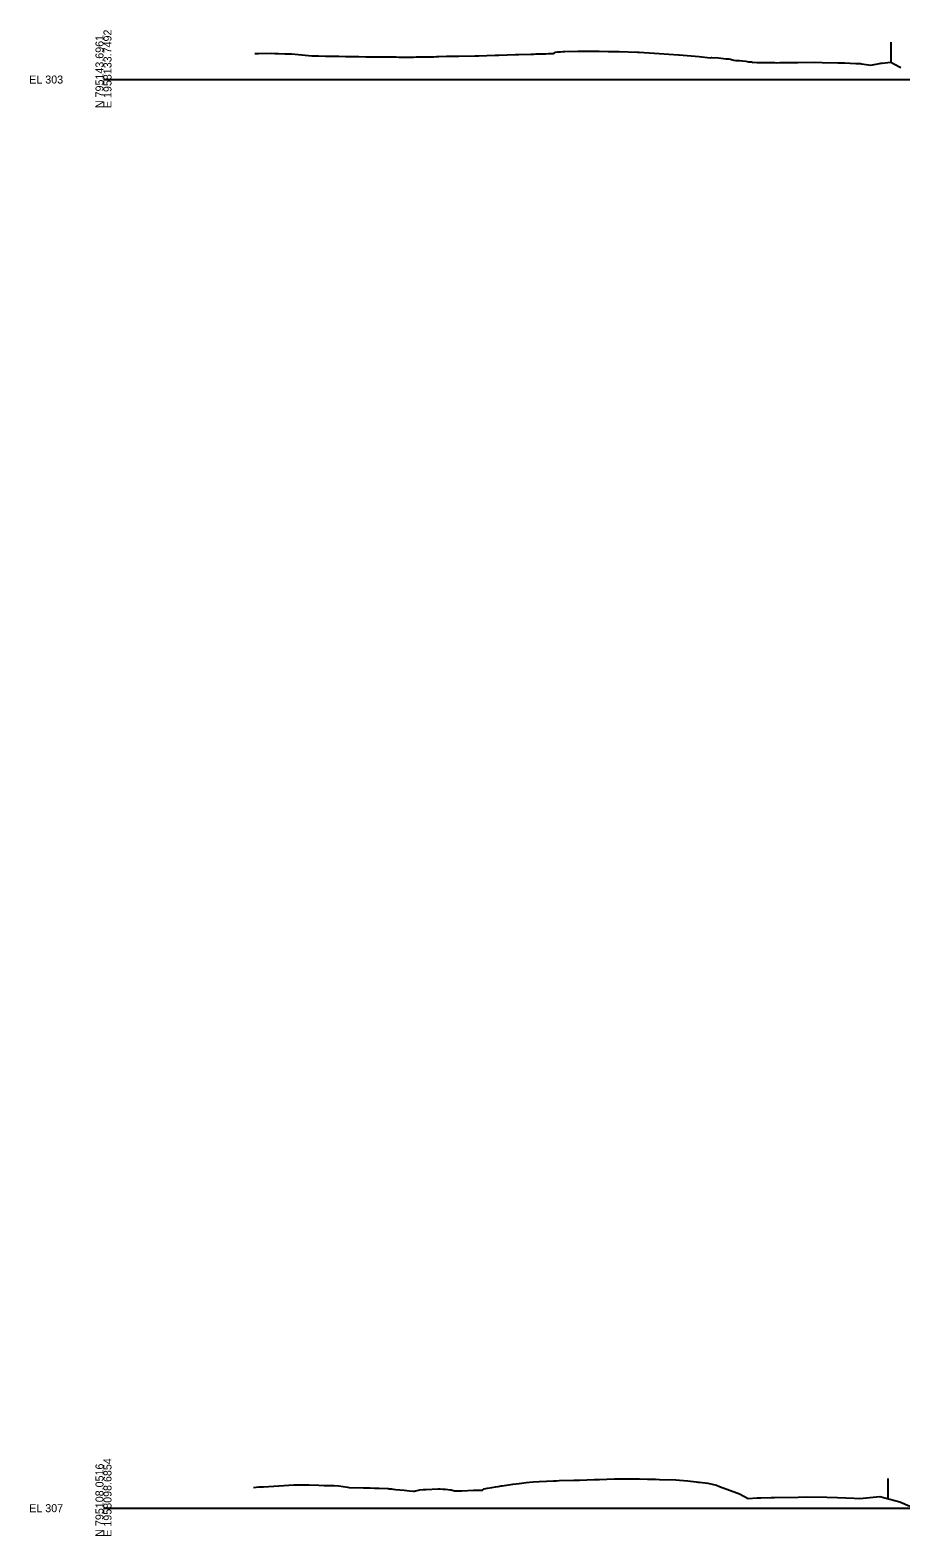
# Model space of a CAD drawing. Extents: x -4026 to 9638, y -10 to 19609.
# Drawn here: x -2026 to -1721, y 2490 to 3017 of the extents above; entities that cross this region are included whole.
import ezdxf

# ---------------------------------------------------------------- set-up
doc = ezdxf.new("R2010")
doc.units = 0
for name, color, linetype in [('Default', 7, 'Continuous'), ('RD_EX_Fence_Other', 7, 'Continuous'), ('RD_GPK_XS_Cell', 7, 'Continuous'), ('RD_XS_ExGround', 7, 'Continuous')]:
    doc.layers.add(name, color=color, linetype=linetype)

msp = doc.modelspace()

# ---------------------------------------------------------------- linework, layer by layer
at = {"layer": 'RD_EX_Fence_Other'}
for p, q in [((-1724.31, 3013.04), (-1724.31, 3006.04)), ((-1725.42, 2510.36), (-1725.42, 2503.36))]:
    msp.add_line(p, q, dxfattribs=at)
at = {"layer": 'RD_GPK_XS_Cell'}
for p, q in [((-2000, 3000), (-1650, 3000)), ((-2000, 2500), (-1650, 2500))]:
    msp.add_line(p, q, dxfattribs=at)
at = {"layer": 'RD_XS_ExGround'}
for points in [[(-1947.07, 3009.09), (-1945.71, 3009.14), (-1941.33, 3009.23), (-1940, 3009.16), (-1938.7, 3009.1), (-1936.47, 3009.01), (-1934.2, 3008.94), (-1931.69, 3008.71), (-1927.07, 3008.3), (-1925.86, 3008.3), (-1924.67, 3008.28), (-1922.32, 3008.22), (-1919.94, 3008.18), (-1918.79, 3008.16), (-1917.66, 3008.13), (-1915.25, 3008.07), (-1912.81, 3008.04), (-1910.64, 3008.01), (-1908.18, 3007.99), (-1905.68, 3007.95), (-1904.65, 3007.94), (-1903.63, 3007.93), (-1901.11, 3007.91), (-1898.55, 3007.9), (-1897.57, 3007.89), (-1896.62, 3007.88), (-1894.04, 3007.86), (-1891.42, 3007.88), (-1890.5, 3007.9), (-1889.6, 3007.91), (-1886.97, 3007.94), (-1884.29, 3007.99), (-1883.43, 3008.01), (-1882.59, 3008.04), (-1879.9, 3008.12), (-1877.16, 3008.16), (-1875.58, 3008.19), (-1870.03, 3008.3), (-1869.29, 3008.32), (-1868.56, 3008.33), (-1865.75, 3008.42), (-1862.9, 3008.52), (-1862.22, 3008.55), (-1861.55, 3008.57), (-1858.68, 3008.65), (-1855.77, 3008.76), (-1854.53, 3008.8), (-1850.37, 3008.89), (-1849.91, 3008.9), (-1849.35, 3008.93), (-1848.68, 3008.96), (-1847.85, 3008.96), (-1846.78, 3008.99), (-1845.12, 3009.05), (-1844.16, 3009.06), (-1843.03, 3009.1), (-1842.6, 3009.12), (-1842.12, 3009.39), (-1841.76, 3009.61), (-1841.1, 3009.66), (-1839.99, 3009.74), (-1839.13, 3009.76), (-1838.43, 3009.77), (-1833.89, 3009.94), (-1827.23, 3009.91), (-1826.86, 3009.93), (-1826.48, 3009.92), (-1823.33, 3009.84), (-1820.12, 3009.8), (-1819.47, 3009.79), (-1812.99, 3009.58), (-1812.45, 3009.56), (-1805.44, 3009.16), (-1798.73, 3008.61), (-1798.42, 3008.59), (-1791.41, 3008.02), (-1787.55, 3007.59), (-1787.09, 3007.74), (-1786.59, 3007.57), (-1785.47, 3007.66), (-1782.1, 3007.28), (-1781.61, 3007.27), (-1781.1, 3007.26), (-1780.52, 3007.11), (-1779.28, 3006.73), (-1778.59, 3006.69), (-1777.85, 3006.63), (-1777.32, 3006.61), (-1776.33, 3006.51), (-1775.12, 3006.38), (-1774.18, 3006.24), (-1773.13, 3006.15), (-1772.79, 3006.01), (-1772.11, 3006.05), (-1771.24, 3006.01), (-1770.38, 3005.98), (-1769.67, 3005.97), (-1766.93, 3005.93), (-1765.79, 3005.92), (-1764.97, 3005.92), (-1764.22, 3005.9), (-1763.15, 3005.96), (-1762.07, 3005.97), (-1756.94, 3006.02), (-1751.04, 3006.07), (-1748.4, 3006.02), (-1742.96, 3005.9), (-1741.31, 3005.87), (-1740.52, 3005.86), (-1736.56, 3005.66), (-1735.55, 3005.61), (-1734.93, 3005.58), (-1734.56, 3005.52), (-1731.4, 3005.03), (-1728.29, 3005.62), (-1727.86, 3005.7), (-1727.43, 3005.76), (-1724.33, 3006.06), (-1721.27, 3004.49), (-1720.79, 3004.2)], [(-1947.48, 2507.24), (-1945.62, 2507.42), (-1943.95, 2507.49), (-1942.25, 2507.61), (-1940.41, 2507.7), (-1938.61, 2507.84), (-1936.88, 2507.91), (-1935.12, 2508.05), (-1933.34, 2508.12), (-1931.6, 2508.23), (-1929.81, 2508.17), (-1927.99, 2508.14), (-1924.58, 2508.09), (-1922.73, 2507.91), (-1920.86, 2507.95), (-1919.2, 2507.89), (-1917.57, 2507.84), (-1914.54, 2507.36), (-1914.02, 2507.29), (-1909, 2507.11), (-1906.6, 2507.13), (-1905.06, 2506.96), (-1903.54, 2506.96), (-1900.35, 2506.87), (-1900.03, 2506.83), (-1899.64, 2506.78), (-1899.15, 2506.74), (-1898.54, 2506.67), (-1897.74, 2506.59), (-1894.72, 2506.28), (-1893.85, 2506.15), (-1892.81, 2506.11), (-1891.52, 2505.91), (-1891.1, 2505.91), (-1890.72, 2506.03), (-1890.19, 2506.22), (-1889.71, 2506.35), (-1889.28, 2506.39), (-1888.11, 2506.49), (-1887.18, 2506.53), (-1882.79, 2506.75), (-1882.08, 2506.72), (-1881.24, 2506.67), (-1880.24, 2506.6), (-1879.49, 2506.57), (-1878.68, 2506.42), (-1878.3, 2506.39), (-1877.06, 2506.08), (-1876.06, 2506.06), (-1875.25, 2506.09), (-1874.56, 2506.09), (-1870.46, 2506.3), (-1869.66, 2506.29), (-1868.63, 2506.33), (-1867.34, 2506.25), (-1866.71, 2506.78), (-1865.55, 2506.98), (-1864.08, 2507.23), (-1862.76, 2507.45), (-1861.87, 2507.6), (-1861.24, 2507.71), (-1860.75, 2507.81), (-1860.38, 2507.88), (-1856.69, 2508.4), (-1855.56, 2508.53), (-1854.44, 2508.68), (-1852.02, 2508.98), (-1849.56, 2509.27), (-1847.43, 2509.39), (-1844.95, 2509.51), (-1842.43, 2509.62), (-1841.41, 2509.6), (-1840.42, 2509.64), (-1835.3, 2509.79), (-1833.4, 2509.86), (-1830.81, 2509.92), (-1828.17, 2510.04), (-1827.27, 2510.06), (-1826.39, 2510.08), (-1823.74, 2510.15), (-1821.04, 2510.24), (-1820.2, 2510.26), (-1819.38, 2510.27), (-1813.91, 2510.32), (-1812.36, 2510.3), (-1809.59, 2510.21), (-1806.78, 2510.12), (-1805.35, 2510.09), (-1799.65, 2509.91), (-1798.34, 2509.85), (-1795.45, 2509.61), (-1792.52, 2509.2), (-1791.92, 2509.12), (-1791.32, 2509.06), (-1788.38, 2508.78), (-1785.39, 2508.03), (-1784.31, 2507.64), (-1778.26, 2505.39), (-1777.29, 2504.99), (-1774.24, 2503.42), (-1771.13, 2503.59), (-1770.7, 2503.6), (-1769.86, 2503.63), (-1766.21, 2503.76), (-1765.12, 2503.79), (-1756.79, 2503.91), (-1753.73, 2503.97), (-1746.76, 2503.85), (-1742.99, 2503.77), (-1737.23, 2503.51), (-1735.21, 2503.44), (-1728.2, 2504.11), (-1721.18, 2502.21), (-1717.67, 2500.72)]]:
    msp.add_lwpolyline(points, dxfattribs=at)

# ---------------------------------------------------------------- texts
at = {"layer": 'Default'}
for p in [(-2000, 3000), (-2000, 2500)]:
    msp.add_text('-', height=0.0001, dxfattribs=at).set_placement(p)
at = {"layer": 'RD_GPK_XS_Cell'}
for s, p in [('N 795143.6961', (-2000, 2990)), ('E 1958133.7492', (-1997.2, 2990)), ('N 795108.0516', (-2000, 2490)), ('E 1958098.6854', (-1997.2, 2490))]:
    msp.add_text(s, height=2.8, rotation=90, dxfattribs=at).set_placement(p)
for s, p in [('EL 303', (-2026, 2998.6)), ('EL 307', (-2026, 2498.6))]:
    msp.add_text(s, height=2.8, dxfattribs=at).set_placement(p)

doc.saveas('drawing.dxf')
